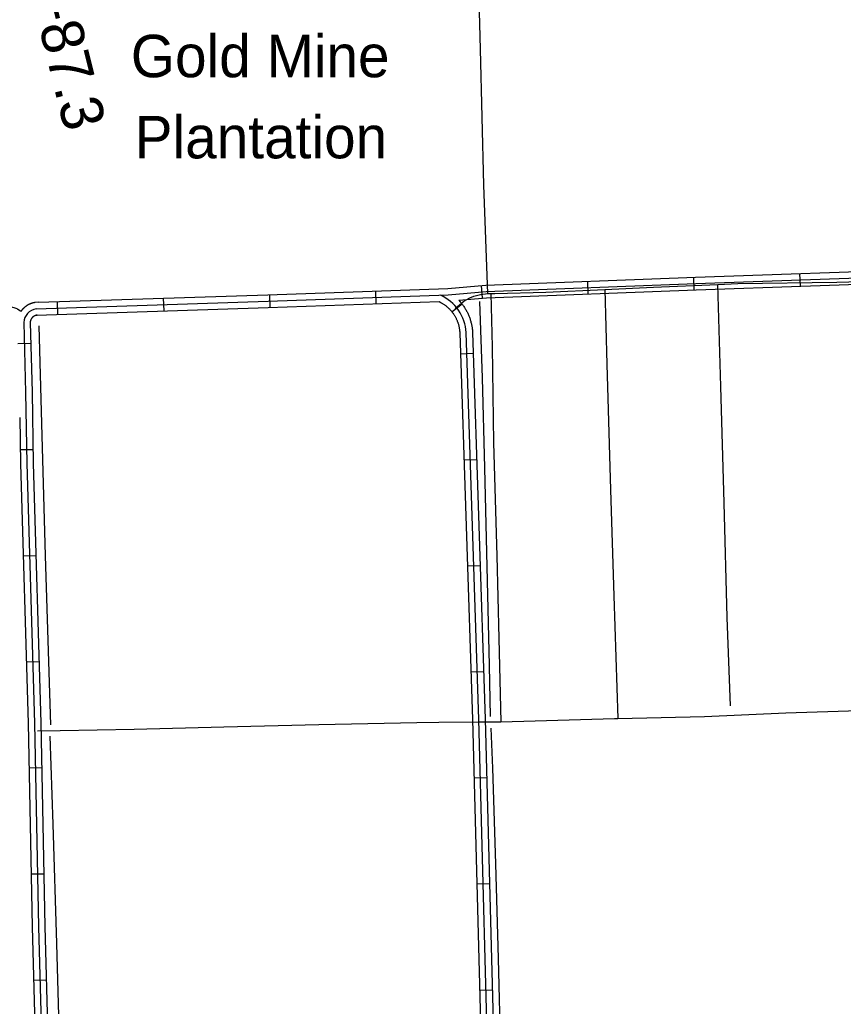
# Model space of a CAD drawing. Extents: x 3508733 to 3546731, y 546897 to 572481.
# Drawn here: x 3537053 to 3538993, y 559192 to 561516 of the extents above; entities that cross this region are included whole.
import ezdxf

# ---------------------------------------------------------------- set-up
doc = ezdxf.new("R2010")
doc.units = 0
for name, color, linetype in [('V-BLDG-IDEN', 7, 'Continuous'), ('V-DTCH-CNTR', 7, 'Continuous'), ('V-ROAD-CNTR', 7, 'Continuous'), ('V-SURV-IDEN', 7, 'Continuous'), ('V-TOPO-SHOR', 7, 'Continuous')]:
    doc.layers.add(name, color=color, linetype=linetype)

msp = doc.modelspace()

# ---------------------------------------------------------------- linework, layer by layer
at = {"layer": 'V-DTCH-CNTR'}
for points in [[(3538156, 560870.9), (3538146.3, 561126.2), (3538138.8, 561447.1), (3538129.6, 561801.8), (3538121.7, 562088.2), (3538115.8, 562303.5), (3538116.6, 562313.1), (3538120.1, 562320), (3538131.9, 562330.9), (3538160.4, 562346.4), (3538314.9, 562404.1), (3538514.4, 562480.5), (3538630.1, 562524.8), (3538644.6, 562528.8), (3538658.4, 562528.6), (3538667.3, 562527.2), (3538679.7, 562521.5), (3538689.3, 562513.1), (3538695.4, 562502.7), (3538738.2, 562385.6), (3538811.9, 562185.5), (3538893, 561969.3), (3538991.6, 561713), (3539094.8, 561435.3)], [(3538078.9, 560835.7), (3538099.8, 560853.4), (3538113.7, 560860.8), (3538123.4, 560864.8), (3538138.6, 560868.8), (3538150.3, 560870.8), (3538156, 560870.9), (3538163, 560871), (3538172.4, 560871.2), (3538292.5, 560874.7), (3538431.5, 560881.1), (3538546.5, 560886.4), (3538698, 560892.7), (3538745.3, 560894.6), (3538977.8, 560898.3), (3539174.5, 560903.7), (3539210.3, 560903.3), (3539244.8, 560900.9), (3539263.4, 560900), (3539275.1, 560899.8), (3539284.1, 560901.8), (3539299.6, 560910.5)], [(3538431.5, 560881.1), (3538436.4, 560704.5), (3538444.9, 560409.1), (3538453.2, 560159.3), (3538462.5, 559870.2)], [(3538728, 559899.7), (3538719.9, 560108.1), (3538712.5, 560378), (3538704.5, 560651.9), (3538698, 560892.7)], [(3538163, 560871), (3538166.4, 560745.4), (3538169.5, 560519.1), (3538176.9, 560253.4), (3538181.7, 560058.1), (3538186.4, 559862.4)], [(3538135, 559862.5), (3538175, 559862.1), (3538186.4, 559862.4), (3538267.4, 559864.5), (3538454.5, 559870.1), (3538462.5, 559870.2), (3538666.3, 559874.6), (3538858.2, 559883.6), (3539104.5, 559891.2), (3539357.1, 559898.8), (3539636.6, 559906.1), (3539653.1, 559906.6), (3539661.4, 559908.6), (3539679.9, 559914.5)], [(3537095.6, 559841), (3537148.7, 559841.8), (3537323.3, 559844.7), (3537534.5, 559850), (3537758, 559855.8), (3537988.5, 559860.9), (3538040.3, 559861), (3538135, 559862.5)]]:
    msp.add_lwpolyline(points, dxfattribs=at)
at = {"layer": 'V-ROAD-CNTR'}
for p, q in [((3538640.5, 560909.5), (3538641.6, 560879.5)), ((3538890.4, 560918.2), (3538891.4, 560888.2)), ((3538140.1, 560890.2), (3538142.8, 560860.4)), ((3538390.7, 560900.2), (3538391.8, 560870.2)), ((3537391.7, 560860.1), (3537392.7, 560830.2)), ((3537641.5, 560868.4), (3537642.6, 560838.4)), ((3537891.4, 560877), (3537892.4, 560847.1)), ((3537141.8, 560851.9), (3537142.8, 560821.9)), ((3538095.3, 560846.3), (3538071.7, 560827.8)), ((3537079.3, 560753.3), (3537049.3, 560752.5)), ((3538121.6, 560729.6), (3538091.6, 560728.6)), ((3537084.9, 560503.3), (3537054.9, 560502.7)), ((3538129.8, 560479.7), (3538099.8, 560478.7)), ((3537091.7, 560253.5), (3537061.7, 560252.7)), ((3538138, 560229.9), (3538108, 560228.9)), ((3537098.9, 560003.6), (3537068.9, 560002.8)), ((3538146.2, 559980), (3538116.2, 559979)), ((3537105.2, 559753.6), (3537075.2, 559753)), ((3538153.5, 559730), (3538123.5, 559729.2)), ((3537110.2, 559503.6), (3537080.2, 559503)), ((3538160.1, 559480.1), (3538130.1, 559479.3)), ((3537116.1, 559253.8), (3537086.1, 559253)), ((3538166.7, 559230.2), (3538136.7, 559229.4))]:
    msp.add_line(p, q, dxfattribs=at)
for points in [[(3537097.3, 560851.1), (3537637.9, 560868.3), (3538061.7, 560882.9), (3538151.2, 560891.3), (3538645.3, 560909.7), (3539185.9, 560928.6), (3539251, 560925.1)], [(3537092.3, 560835.3), (3537638.4, 560853.3), (3538062.7, 560868), (3538152.2, 560876.3), (3538645.9, 560894.7), (3539185.8, 560913.5), (3539250.2, 560910.1)], [(3538087.7, 560855.2), (3538153.1, 560861.3), (3538646.4, 560879.7), (3539185.7, 560898.5), (3539230.3, 560896.2)], [(3536991.5, 560850.9), (3537039.9, 560838.4), (3537044.2, 560836.7), (3537048, 560834.9), (3537051.7, 560832.8), (3537055.2, 560830.5), (3537056.6, 560829.4)], [(3537097.3, 560851.1), (3537089.7, 560850), (3537088.9, 560849.9), (3537088, 560849.7), (3537087.2, 560849.6), (3537086.4, 560849.4), (3537085.5, 560849.2), (3537084.7, 560849), (3537083.8, 560848.8), (3537083, 560848.5), (3537082.2, 560848.3), (3537081.4, 560848), (3537080.6, 560847.7), (3537079.8, 560847.5), (3537079, 560847.2), (3537078.2, 560846.8), (3537077.4, 560846.5), (3537076.6, 560846.2), (3537075.8, 560845.8), (3537075, 560845.4), (3537074.3, 560845), (3537073.6, 560844.6), (3537072.8, 560844.2), (3537072, 560843.8), (3537071.3, 560843.3), (3537070.6, 560842.9), (3537069.8, 560842.4), (3537069.2, 560841.9), (3537068.5, 560841.4), (3537067.7, 560840.9), (3537067.1, 560840.4), (3537066.4, 560839.9), (3537065.7, 560839.3), (3537065.1, 560838.8), (3537064.4, 560838.2), (3537063.8, 560837.7), (3537063.2, 560837.1), (3537062.5, 560836.5), (3537061.9, 560835.9), (3537061.3, 560835.3), (3537060.8, 560834.6), (3537060.2, 560834), (3537059.6, 560833.3), (3537059.1, 560832.7), (3537058.6, 560832), (3537058, 560831.3), (3537057.5, 560830.6), (3537057, 560830), (3537056.5, 560829.3), (3537056.3, 560828.9)], [(3537092.8, 560820.2), (3537638.9, 560838.3), (3538041.5, 560852.2)], [(3538041.5, 560852.2), (3538045.2, 560850.2), (3538046.5, 560849.5), (3538047.8, 560848.8), (3538049.1, 560848), (3538050.4, 560847.2), (3538051.6, 560846.4), (3538052.9, 560845.5), (3538054.1, 560844.7), (3538055.3, 560843.8), (3538056.5, 560842.9), (3538057.7, 560842), (3538058.8, 560841), (3538060, 560840), (3538061.1, 560839.1), (3538062.2, 560838.1), (3538063.3, 560837), (3538064.4, 560836), (3538065.5, 560834.9), (3538066.5, 560833.8), (3538067.5, 560832.8), (3538068.6, 560831.6), (3538069.5, 560830.5), (3538070.5, 560829.4), (3538071.5, 560828.2), (3538072.4, 560827), (3538073.2, 560825.8), (3538074.2, 560824.6), (3538075, 560823.4), (3538075.8, 560822.1), (3538076.6, 560820.9), (3538077.5, 560819.6), (3538078.2, 560818.3), (3538079, 560817), (3538079.7, 560815.7), (3538080.4, 560814.4), (3538081.1, 560813), (3538081.7, 560811.7), (3538082.4, 560810.3), (3538083, 560809), (3538083.6, 560807.6), (3538084.1, 560806.2), (3538084.7, 560804.8), (3538085.2, 560803.4), (3538085.7, 560802), (3538086.1, 560800.5), (3538086.6, 560799.1), (3538087, 560797.6), (3538087.4, 560796.2), (3538087.7, 560794.8), (3538088.1, 560793.3), (3538088.4, 560791.8), (3538088.7, 560790.3), (3538088.9, 560788.9), (3538089.1, 560787.4), (3538089.4, 560785.9), (3538089.5, 560784.4), (3538089.7, 560782.9), (3538089.8, 560781.4), (3538089.9, 560779.9), (3538090, 560778.3)], [(3538087.7, 560855.2), (3538091, 560851.5), (3538092.4, 560850), (3538093.6, 560848.4), (3538094.9, 560846.9), (3538096.2, 560845.3), (3538097.4, 560843.6), (3538098.6, 560842), (3538099.7, 560840.3), (3538100.9, 560838.6), (3538102, 560837), (3538103, 560835.3), (3538104.1, 560833.5), (3538105.1, 560831.8), (3538106.1, 560830), (3538107, 560828.2), (3538107.9, 560826.4), (3538108.8, 560824.6), (3538109.7, 560822.8), (3538110.5, 560820.9), (3538111.3, 560819), (3538112, 560817.2), (3538112.8, 560815.3), (3538113.5, 560813.4), (3538114.1, 560811.4), (3538114.7, 560809.5), (3538115.3, 560807.6), (3538115.9, 560805.7), (3538116.4, 560803.7), (3538116.9, 560801.7), (3538117.3, 560799.8), (3538117.8, 560797.8), (3538118.2, 560795.8), (3538118.5, 560793.8), (3538118.8, 560791.8), (3538119.1, 560789.8), (3538119.4, 560787.8), (3538119.6, 560785.8), (3538119.7, 560783.8), (3538119.9, 560781.7), (3538120, 560779.8)], [(3537092.8, 560820.2), (3537094.2, 560820.4), (3537093.8, 560820.3), (3537093.5, 560820.3), (3537093.2, 560820.2), (3537092.9, 560820.1), (3537092.5, 560820), (3537092.2, 560820), (3537091.9, 560819.9), (3537091.6, 560819.8), (3537091.2, 560819.7), (3537090.9, 560819.6), (3537090.6, 560819.5), (3537090.3, 560819.4), (3537090, 560819.2), (3537089.7, 560819.1), (3537089.4, 560819), (3537089, 560818.8), (3537088.8, 560818.7), (3537088.5, 560818.6), (3537088.1, 560818.4), (3537087.8, 560818.2), (3537087.6, 560818.1), (3537087.3, 560817.9), (3537087, 560817.7), (3537086.7, 560817.6), (3537086.5, 560817.4), (3537086.1, 560817.2), (3537085.9, 560817), (3537085.6, 560816.8), (3537085.3, 560816.6), (3537085.1, 560816.4), (3537084.8, 560816.2), (3537084.5, 560816), (3537084.3, 560815.8), (3537084.1, 560815.5), (3537083.8, 560815.3), (3537083.6, 560815.1), (3537083.4, 560814.9), (3537083.1, 560814.6), (3537082.9, 560814.4), (3537082.7, 560814.1), (3537082.5, 560813.9), (3537082.2, 560813.6), (3537082, 560813.3), (3537081.8, 560813.1), (3537081.6, 560812.8), (3537081.4, 560812.5), (3537081.2, 560812.3), (3537081.1, 560812), (3537080.9, 560811.7), (3537080.7, 560811.4), (3537080.5, 560811.1), (3537080.4, 560810.9), (3537080.2, 560810.6), (3537080, 560810.3), (3537079.9, 560810), (3537079.7, 560809.7), (3537079.6, 560809.4), (3537079.5, 560809.1), (3537079.3, 560808.8), (3537079.2, 560808.4), (3537079.1, 560808.1), (3537079, 560807.8), (3537078.9, 560807.5), (3537078.7, 560807.2), (3537078.6, 560806.8), (3537078.5, 560806.5), (3537078.5, 560806.2), (3537078.4, 560805.9), (3537078.3, 560805.6), (3537078.2, 560805.2), (3537078.2, 560804.9), (3537078.1, 560804.6), (3537078.1, 560804.3), (3537078, 560803.9), (3537078, 560803.6), (3537078, 560803.3), (3537077.9, 560802.9), (3537077.9, 560802.6), (3537077.9, 560802.2)], [(3537062.9, 560802.9), (3537067.4, 560638.4), (3537070.5, 560470.6), (3537088, 559859.2), (3537097.7, 559379.2), (3537112.4, 558836.8), (3537128.6, 558350.9), (3537145.6, 557850.8)], [(3537062.9, 560802.9), (3537067.4, 560638.4), (3537070.5, 560470.6), (3537088, 559859.2), (3537097.7, 559379.2), (3537112.4, 558836.8), (3537128.6, 558350.9), (3537145.6, 557850.8)], [(3537077.9, 560803.3), (3537082.4, 560638.7), (3537085.5, 560470.9), (3537103, 559859.5), (3537112.7, 559379.6), (3537126.9, 558855.6)], [(3538090, 560778.6), (3538119.9, 559867.5), (3538145.7, 558887.1), (3538146, 558877.4)], [(3538216.1, 556883.3), (3538191, 557870.9), (3538160.7, 558887.5), (3538134.9, 559867.9), (3538105, 560779.1)], [(3538120, 560779.6), (3538149.9, 559868.3), (3538175.7, 558887.9), (3538206, 557871.3), (3538231.1, 556881.4)], [(3537053.5, 560579), (3537055.5, 560470.2), (3537073, 559858.8), (3537082.7, 559378.9), (3537096.9, 558855.3)]]:
    msp.add_lwpolyline(points, dxfattribs=at)
for centre, radius, start, end in [((3538004.1, 560774.7), 100.9, 2.4677, 66.5225), ((3537097, 560801.4), 34.1, 97.8458, 177.5224)]:
    msp.add_arc(centre, radius, start, end, dxfattribs=at)
at = {"layer": 'V-TOPO-SHOR'}
for points in [[(3538136.6, 560852.5), (3538142.9, 560672.3), (3538148.2, 560460.5), (3538159, 559994.7), (3538161.8, 559874.6)], [(3537098.7, 560795.5), (3537104.4, 560565), (3537113.4, 560253.1), (3537125.6, 559854.8)], [(3538163.5, 559847), (3538166.7, 559753.1), (3538173.8, 559527.4), (3538180.4, 559304.5), (3538186.2, 559081.6), (3538192.3, 558878)], [(3537124.7, 559828.6), (3537131.4, 559620.9), (3537140, 559340), (3537146.5, 559112.9), (3537152.6, 558846.6)]]:
    msp.add_lwpolyline(points, dxfattribs=at)

# ---------------------------------------------------------------- texts
at = {"layer": 'V-BLDG-IDEN'}
for s, p in [('Gold Mine', (3537315.2, 561380.8)), ('Plantation', (3537324.2, 561189.7))]:
    msp.add_text(s, height=100, dxfattribs=at).set_placement(p)
at = {"layer": 'V-SURV-IDEN'}
msp.add_text('2134+87.3', height=100, rotation=283.9407, dxfattribs=at).set_placement((3537007.6, 561865.8))

doc.saveas('drawing.dxf')
